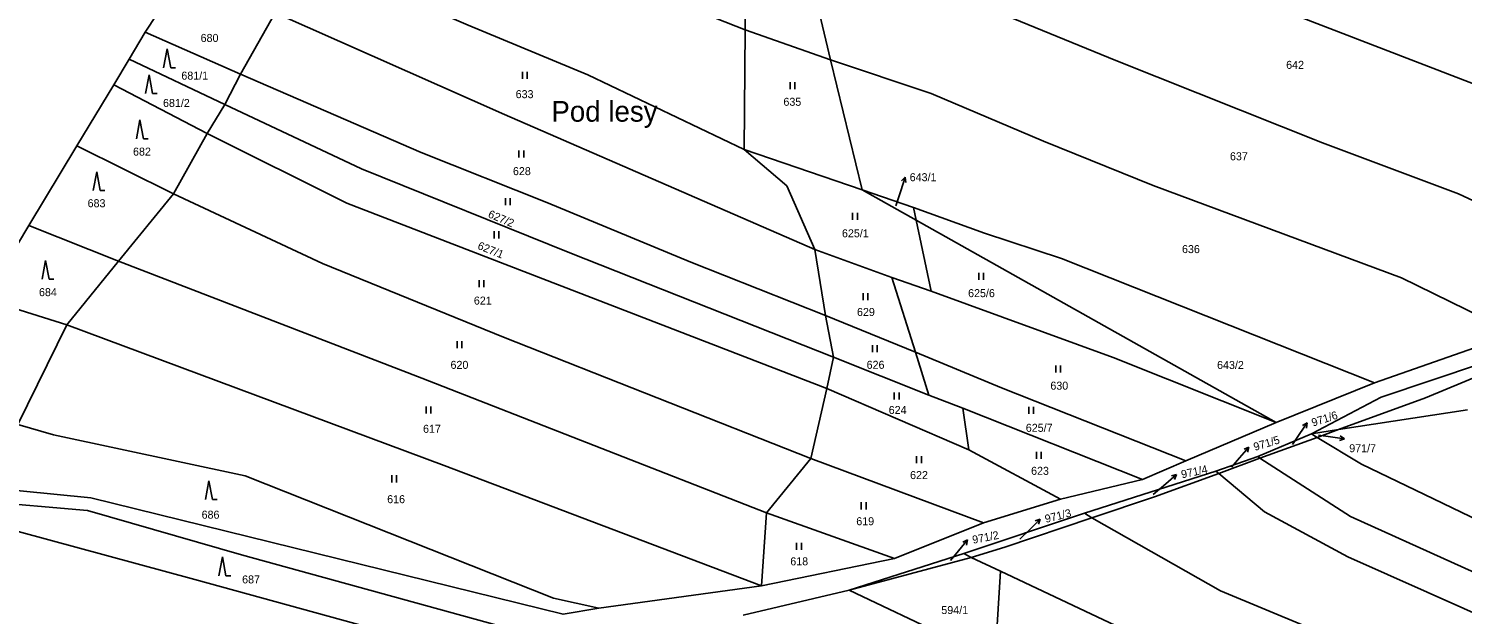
# Model space of a CAD drawing. Extents: x -7483133 to -743907, y -11317770 to -1129777.
# Drawn here: x -748843.6 to -748539, y -1130997.2 to -1130872.8 of the extents above; entities that cross this region are included whole.
import ezdxf

# ---------------------------------------------------------------- set-up
doc = ezdxf.new("R2010")
doc.units = 0
for name, color, linetype in [('Hranice parcel', 7, 'Continuous'), ('Parcelní čísla', 7, 'Continuous'), ('Pop  PČ popisy', 7, 'Continuous'), ('Značky kultur', 7, 'Continuous')]:
    doc.layers.add(name, color=color, linetype=linetype)

msp = doc.modelspace()

# ---------------------------------------------------------------- linework, layer by layer
at = {"layer": 'Hranice parcel'}
for p, q in [((-748691.29, -1130849.38), (-748691.38, -1130873.01)), ((-748818.81, -1130873.52), (-748810.46, -1130860.65)), ((-748791.23, -1130869.37), (-748798.57, -1130882.46)), ((-748822.26, -1130879.25), (-748818.81, -1130873.52)), ((-748818.81, -1130873.52), (-748798.57, -1130882.46)), ((-748691.56, -1130898.44), (-748691.38, -1130873.01)), ((-748673.21, -1130879.38), (-748691.38, -1130873.01)), ((-748825.52, -1130884.67), (-748822.26, -1130879.25)), ((-748822.26, -1130879.25), (-748801.95, -1130888.88)), ((-748666.52, -1130906.98), (-748673.21, -1130879.38)), ((-748798.57, -1130882.46), (-748801.95, -1130888.88)), ((-748833.33, -1130897.65), (-748825.52, -1130884.67)), ((-748825.52, -1130884.67), (-748805.64, -1130895.06)), ((-748801.95, -1130888.88), (-748805.64, -1130895.06)), ((-748805.64, -1130895.06), (-748812.83, -1130907.88)), ((-748843.53, -1130914.6), (-748833.33, -1130897.65)), ((-748833.33, -1130897.65), (-748812.83, -1130907.88)), ((-748666.52, -1130906.98), (-748691.56, -1130898.44)), ((-748812.83, -1130907.88), (-748824.49, -1130922.2)), ((-748655.04, -1130913.44), (-748666.52, -1130906.98)), ((-748666.52, -1130906.98), (-748655.57, -1130910.8)), ((-748655.04, -1130913.44), (-748655.57, -1130910.8)), ((-748852.94, -1130930.24), (-748843.53, -1130914.6)), ((-748843.53, -1130914.6), (-748824.49, -1130922.2)), ((-748651.83, -1130928.55), (-748655.04, -1130913.44)), ((-748578.54, -1130956.49), (-748655.04, -1130913.44)), ((-748676.59, -1130919.71), (-748660.16, -1130925.62)), ((-748674.28, -1130933.73), (-748676.59, -1130919.71)), ((-748824.49, -1130922.2), (-748835.48, -1130935.7)), ((-748660.16, -1130925.62), (-748651.83, -1130928.55)), ((-748655.19, -1130941.48), (-748660.16, -1130925.62)), ((-748852.94, -1130930.24), (-748835.48, -1130935.7)), ((-748835.48, -1130935.7), (-748845.89, -1130956.91)), ((-748655.19, -1130941.48), (-748674.28, -1130933.73)), ((-748674.28, -1130933.73), (-748672.59, -1130942.59)), ((-748557.64, -1130948.06), (-748527.72, -1130937.53)), ((-748655.19, -1130941.48), (-748652.32, -1130950.63)), ((-748672.59, -1130942.59), (-748673.99, -1130949.21)), ((-748652.32, -1130950.63), (-748672.59, -1130942.59)), ((-748578.54, -1130956.49), (-748557.64, -1130948.06)), ((-748677.43, -1130964.14), (-748673.99, -1130949.21)), ((-748643.86, -1130962.26), (-748673.99, -1130949.21)), ((-748645.13, -1130953.44), (-748652.32, -1130950.63)), ((-748645.13, -1130953.44), (-748643.86, -1130962.26)), ((-748606.96, -1130968.54), (-748645.13, -1130953.44)), ((-748565.28, -1130957.97), (-748537.89, -1130953.74)), ((-748597.75, -1130964.64), (-748578.54, -1130956.49)), ((-748582.43, -1130963.71), (-748571.03, -1130958.84)), ((-748569.8, -1130959.62), (-748581.99, -1130964.07)), ((-748565.28, -1130957.97), (-748571.03, -1130958.84)), ((-748569.8, -1130959.62), (-748571.03, -1130958.84)), ((-748565.28, -1130957.97), (-748569.8, -1130959.62)), ((-748624.37, -1130972.78), (-748643.86, -1130962.26)), ((-748677.43, -1130964.14), (-748686.82, -1130975.66)), ((-748640.75, -1130977.76), (-748677.43, -1130964.14)), ((-748606.96, -1130968.54), (-748597.75, -1130964.64)), ((-748591.34, -1130966.78), (-748582.43, -1130963.71)), ((-748581.99, -1130964.07), (-748590.75, -1130967.27)), ((-748581.99, -1130964.07), (-748582.43, -1130963.71)), ((-748624.37, -1130972.78), (-748606.96, -1130968.54)), ((-748619.29, -1130975.71), (-748591.34, -1130966.78)), ((-748590.75, -1130967.27), (-748591.34, -1130966.78)), ((-748640.75, -1130977.76), (-748624.37, -1130972.78)), ((-748687.86, -1130991.16), (-748686.82, -1130975.66)), ((-748659.6, -1130985.35), (-748686.82, -1130975.66)), ((-748659.6, -1130985.35), (-748640.75, -1130977.76)), ((-748644.89, -1130984.3), (-748619.29, -1130975.71)), ((-748617.7, -1130976.74), (-748619.29, -1130975.71)), ((-748669.28, -1130992.07), (-748644.89, -1130984.3)), ((-748643.37, -1130985.15), (-748644.89, -1130984.3)), ((-748687.86, -1130991.16), (-748659.6, -1130985.35)), ((-748643.37, -1130985.15), (-748669.28, -1130992.07)), ((-748637.1, -1130988.07), (-748643.37, -1130985.15)), ((-748638.28, -1131006.71), (-748637.1, -1130988.07)), ((-748722.45, -1130995.95), (-748687.86, -1130991.16)), ((-748669.28, -1130992.07), (-748691.81, -1130997.44)), ((-748669.28, -1130992.07), (-748648.09, -1131002.15))]:
    msp.add_line(p, q, dxfattribs=at)
for points in [[(-748476.62, -1130910.98), (-748520.26, -1130890.78), (-748603.55, -1130858.65), (-748669.5, -1130833.07)], [(-748691.38, -1130873.01), (-748733.87, -1130856.25), (-748780.28, -1130837.27)], [(-748681.37, -1130852.94), (-748675.59, -1130869.57), (-748673.21, -1130879.38)], [(-748501.67, -1130925.66), (-748539.81, -1130907.88), (-748568.68, -1130897.02), (-748612.61, -1130879.56), (-748648.46, -1130864.82), (-748681.37, -1130852.94)], [(-748691.56, -1130898.44), (-748724.77, -1130882.55), (-748750.23, -1130872.02), (-748786.7, -1130856.35)], [(-748676.59, -1130919.71), (-748742.5, -1130891), (-748791.23, -1130869.37)], [(-748527.72, -1130937.53), (-748551.88, -1130925.74), (-748604.69, -1130906.09), (-748627.96, -1130896.65), (-748651.82, -1130886.51), (-748673.21, -1130879.38)], [(-748674.28, -1130933.73), (-748702.92, -1130922.4), (-748733.51, -1130909.72), (-748760.2, -1130899.08), (-748798.57, -1130882.46)], [(-748672.59, -1130942.59), (-748728.61, -1130920.39), (-748772.9, -1130902.53), (-748801.95, -1130888.88)], [(-748673.99, -1130949.21), (-748734.35, -1130925.92), (-748775.96, -1130909.83), (-748805.64, -1130895.06)], [(-748691.56, -1130898.44), (-748682.52, -1130906.16), (-748676.59, -1130919.71)], [(-748677.43, -1130964.14), (-748742.72, -1130938.33), (-748781.18, -1130922.64), (-748812.83, -1130907.88)], [(-748571.03, -1130958.84), (-748556.25, -1130951.09), (-748524.38, -1130940.39), (-748502.11, -1130930.25), (-748493.27, -1130925.55), (-748485.55, -1130920.61), (-748473.74, -1130913.87), (-748443.77, -1130907.57)], [(-748443.77, -1130907.57), (-748473.57, -1130919.12), (-748507.59, -1130934.95), (-748546.84, -1130951.23), (-748565.28, -1130957.97)], [(-748655.57, -1130910.8), (-748640.51, -1130916.19), (-748624.12, -1130921.59), (-748557.64, -1130948.06)], [(-748686.82, -1130975.66), (-748760.05, -1130947.07), (-748824.49, -1130922.2)], [(-748651.83, -1130928.55), (-748613.14, -1130942.66), (-748578.54, -1130956.49)], [(-748687.86, -1130991.16), (-748755.34, -1130965.63), (-748835.48, -1130935.7)], [(-748597.75, -1130964.64), (-748636.89, -1130949.07), (-748655.19, -1130941.48)], [(-748845.89, -1130956.91), (-748838.31, -1130959.08), (-748797.6, -1130967.82), (-748732.08, -1130993.78), (-748722.45, -1130995.95)], [(-748401.59, -1131039.86), (-748482.79, -1131002.25), (-748525.81, -1130981.98), (-748560.43, -1130965.34), (-748569.8, -1130959.62)], [(-748408.58, -1131046.09), (-748444.76, -1131028.43), (-748487.86, -1131009.7), (-748519.33, -1130996.05), (-748562.72, -1130976.46), (-748581.99, -1130964.07)], [(-748875.49, -1130968.04), (-748830.4, -1130972.44), (-748730.06, -1130997.2), (-748722.45, -1130995.95)], [(-748590.75, -1130967.27), (-748604.42, -1130972.26), (-748617.7, -1130976.74)], [(-748417.45, -1131050.74), (-748429.46, -1131045.22), (-748443.17, -1131038.57), (-748447.76, -1131036), (-748521.8, -1131003.51), (-748563.34, -1130984.99), (-748581.03, -1130975.42), (-748590.75, -1130967.27)], [(-748718.11, -1131005.41), (-748734.03, -1131002.28), (-748798.34, -1130984.6), (-748831.06, -1130975.19), (-748876.9, -1130971.17)], [(-748876.9, -1130971.17), (-748808.26, -1130989.85), (-748721.27, -1131013.77)], [(-748617.7, -1130976.74), (-748636.18, -1130982.97), (-748643.37, -1130985.15)], [(-748433.86, -1131062.5), (-748469.72, -1131045.54), (-748503.59, -1131029.98), (-748535.57, -1131015.06), (-748590.35, -1130992.22), (-748617.7, -1130976.74)], [(-748637.1, -1130988.07), (-748580.62, -1131014.77), (-748540.84, -1131031.61), (-748501.83, -1131050.32), (-748475.33, -1131062.6), (-748443.88, -1131076.03)]]:
    msp.add_lwpolyline(points, dxfattribs=at)
at = {"layer": 'Pop  PČ popisy'}
for p, q in [((-748658.31, -1130907.19), (-748657.38, -1130904.34)), ((-748657.38, -1130904.34), (-748658.17, -1130905.13)), ((-748657.38, -1130904.34), (-748657.22, -1130905.44)), ((-748659.35, -1130910.44), (-748658.31, -1130907.19)), ((-748573.65, -1130959.02), (-748571.97, -1130956.53)), ((-748571.97, -1130956.53), (-748572.95, -1130957.08)), ((-748571.97, -1130956.53), (-748572.12, -1130957.64)), ((-748575.07, -1130961.12), (-748573.65, -1130959.02)), ((-748569.54, -1130959.13), (-748566.98, -1130959.5)), ((-748566.98, -1130959.5), (-748564.01, -1130959.92)), ((-748564.01, -1130959.92), (-748565.07, -1130960.27)), ((-748564.01, -1130959.92), (-748564.93, -1130959.28)), ((-748586.29, -1130963.95), (-748584.32, -1130961.69)), ((-748584.32, -1130961.69), (-748585.36, -1130962.11)), ((-748584.32, -1130961.69), (-748584.6, -1130962.77)), ((-748588.06, -1130965.95), (-748586.29, -1130963.95)), ((-748602, -1130969.47), (-748599.7, -1130967.54)), ((-748599.7, -1130967.54), (-748600.79, -1130967.8)), ((-748599.7, -1130967.54), (-748600.15, -1130968.57)), ((-748604.67, -1130971.74), (-748602, -1130969.47)), ((-748630.8, -1130979.1), (-748628.68, -1130976.98)), ((-748628.68, -1130976.98), (-748629.74, -1130977.33)), ((-748628.68, -1130976.98), (-748629.03, -1130978.04)), ((-748646.02, -1130983.71), (-748644.09, -1130981.41)), ((-748644.09, -1130981.41), (-748645.12, -1130981.86)), ((-748644.09, -1130981.41), (-748644.35, -1130982.5)), ((-748633, -1130981.27), (-748630.8, -1130979.1)), ((-748647.75, -1130985.76), (-748646.02, -1130983.71))]:
    msp.add_line(p, q, dxfattribs=at)
at = {"layer": 'Značky kultur'}
for p, q in [((-748814.17, -1130877.06), (-748814.92, -1130881.06)), ((-748813.42, -1130881.06), (-748814.17, -1130877.06)), ((-748813.42, -1130881.06), (-748812.42, -1130881.06)), ((-748818.01, -1130882.56), (-748818.76, -1130886.56)), ((-748817.26, -1130886.56), (-748818.01, -1130882.56)), ((-748738.65, -1130883.41), (-748738.65, -1130881.91)), ((-748737.65, -1130883.41), (-748737.65, -1130881.91)), ((-748681.8, -1130885.6), (-748681.8, -1130884.1)), ((-748680.8, -1130885.6), (-748680.8, -1130884.1)), ((-748817.26, -1130886.56), (-748816.26, -1130886.56)), ((-748819.95, -1130892.15), (-748820.7, -1130896.15)), ((-748819.2, -1130896.15), (-748819.95, -1130892.15)), ((-748819.2, -1130896.15), (-748818.2, -1130896.15)), ((-748739.42, -1130900.16), (-748739.42, -1130898.66)), ((-748738.42, -1130900.16), (-748738.42, -1130898.66)), ((-748829.14, -1130903.16), (-748829.89, -1130907.16)), ((-748828.39, -1130907.16), (-748829.14, -1130903.16)), ((-748828.39, -1130907.16), (-748827.39, -1130907.16)), ((-748742.31, -1130910.29), (-748742.31, -1130908.79)), ((-748741.31, -1130910.29), (-748741.31, -1130908.79)), ((-748668.52, -1130913.4), (-748668.52, -1130911.9)), ((-748667.52, -1130913.4), (-748667.52, -1130911.9)), ((-748744.72, -1130917.33), (-748744.72, -1130915.83)), ((-748743.72, -1130917.33), (-748743.72, -1130915.83)), ((-748839.99, -1130922.01), (-748840.74, -1130926.01)), ((-748839.24, -1130926.01), (-748839.99, -1130922.01)), ((-748839.24, -1130926.01), (-748838.24, -1130926.01)), ((-748747.87, -1130927.73), (-748747.87, -1130926.23)), ((-748746.87, -1130927.73), (-748746.87, -1130926.23)), ((-748641.71, -1130926.15), (-748641.71, -1130924.65)), ((-748640.71, -1130926.15), (-748640.71, -1130924.65)), ((-748666.28, -1130930.46), (-748666.28, -1130928.96)), ((-748665.28, -1130930.46), (-748665.28, -1130928.96)), ((-748752.56, -1130940.64), (-748752.56, -1130939.14)), ((-748751.56, -1130940.64), (-748751.56, -1130939.14)), ((-748664.31, -1130941.51), (-748664.31, -1130940.01)), ((-748663.31, -1130941.51), (-748663.31, -1130940.01)), ((-748625.33, -1130945.86), (-748625.33, -1130944.36)), ((-748624.33, -1130945.86), (-748624.33, -1130944.36)), ((-748659.67, -1130951.55), (-748659.67, -1130950.05)), ((-748658.67, -1130951.55), (-748658.67, -1130950.05)), ((-748759.12, -1130954.53), (-748759.12, -1130953.03)), ((-748758.12, -1130954.53), (-748758.12, -1130953.03)), ((-748631.09, -1130954.6), (-748631.09, -1130953.1)), ((-748630.09, -1130954.6), (-748630.09, -1130953.1)), ((-748629.44, -1130964.17), (-748629.44, -1130962.67)), ((-748628.44, -1130964.17), (-748628.44, -1130962.67)), ((-748654.92, -1130965.12), (-748654.92, -1130963.62)), ((-748653.92, -1130965.12), (-748653.92, -1130963.62)), ((-748805.29, -1130968.86), (-748806.04, -1130972.86)), ((-748804.54, -1130972.86), (-748805.29, -1130968.86)), ((-748766.41, -1130969.18), (-748766.41, -1130967.68)), ((-748765.41, -1130969.18), (-748765.41, -1130967.68)), ((-748804.54, -1130972.86), (-748803.54, -1130972.86)), ((-748666.68, -1130974.92), (-748666.68, -1130973.42)), ((-748665.68, -1130974.92), (-748665.68, -1130973.42)), ((-748680.42, -1130983.52), (-748680.42, -1130982.02)), ((-748679.42, -1130983.52), (-748679.42, -1130982.02)), ((-748802.42, -1130985.04), (-748803.17, -1130989.04)), ((-748801.67, -1130989.04), (-748802.42, -1130985.04)), ((-748801.67, -1130989.04), (-748800.67, -1130989.04))]:
    msp.add_line(p, q, dxfattribs=at)

# ---------------------------------------------------------------- texts
at = {"layer": 'Parcelní čísla'}
for s, p in [('680', (-748807.06, -1130875.58)), ('642', (-748576.41, -1130881.3)), ('681/1', (-748811.15, -1130883.59)), ('633', (-748740.12, -1130887.53)), ('681/2', (-748815.05, -1130889.4)), ('635', (-748683.23, -1130889.15)), ('682', (-748821.42, -1130899.74)), ('637', (-748588.35, -1130900.73)), ('628', (-748740.7, -1130903.89)), ('643/1', (-748656.4, -1130905.18)), ('683', (-748831.07, -1130910.71)), ('625/1', (-748670.79, -1130917.1)), ('636', (-748598.54, -1130920.46)), ('684', (-748841.4, -1130929.61)), ('621', (-748749, -1130931.4)), ('625/6', (-748643.99, -1130929.82)), ('629', (-748667.6, -1130933.82)), ('620', (-748753.96, -1130945.06)), ('626', (-748665.55, -1130945.05)), ('643/2', (-748591.09, -1130945.09)), ('630', (-748626.51, -1130949.48)), ('624', (-748660.86, -1130954.65)), ('617', (-748759.8, -1130958.65)), ('625/7', (-748631.73, -1130958.44)), ('971/7', (-748563.01, -1130962.78)), ('623', (-748630.61, -1130967.58)), ('622', (-748656.32, -1130968.48)), ('616', (-748767.42, -1130973.61)), ('686', (-748806.85, -1130976.9)), ('619', (-748667.75, -1130978.29)), ('618', (-748681.77, -1130986.82)), ('687', (-748798.24, -1130990.66)), ('594/1', (-748649.68, -1130997.17))]:
    msp.add_text(s, height=1.7, dxfattribs=at).set_placement(p)
for s, rotation, p in [('627/2', 337, (-748746.14, -1130912.78)), ('627/1', 338, (-748748.36, -1130919.52)), ('971/6', 18, (-748570.7, -1130957.35)), ('971/5', 17, (-748583.05, -1130962.51)), ('971/4', 12, (-748598.54, -1130968.35)), ('971/3', 14, (-748627.45, -1130977.81)), ('971/2', 11, (-748642.93, -1130982.25))]:
    msp.add_text(s, height=1.7, rotation=rotation, dxfattribs=at).set_placement(p)
at = {"layer": 'Pop  PČ popisy'}
msp.add_text('Pod lesy', height=4.4, dxfattribs=at).set_placement((-748732.54, -1130892.53))

doc.saveas('drawing.dxf')
